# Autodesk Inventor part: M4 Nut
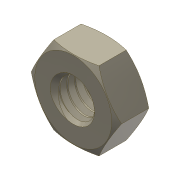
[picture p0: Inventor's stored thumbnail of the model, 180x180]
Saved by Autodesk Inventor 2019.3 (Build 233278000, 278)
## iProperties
Created: 2012-09
Part Number: M4 Nut
Material: Ogólny
Document SubType Name: Modeling
Designer: CADENGINEERING4
Density: 1 g/cm^3
Appearance: Jasnobeżowa
Author: CADENGINEERING4
Revision Number: ÈÎºÎ
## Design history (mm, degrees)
feature "ÇÐ³ý-É¨Ãè1"
node "Bryła1"
